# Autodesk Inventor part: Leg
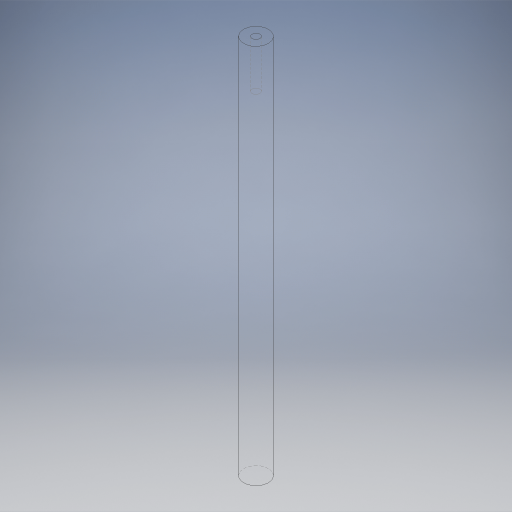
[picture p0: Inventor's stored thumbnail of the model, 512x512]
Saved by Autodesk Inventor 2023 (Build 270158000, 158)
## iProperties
Created: 2024-01
Part Number: Leg
Material: Generic
Document SubType Name: Modeling
Designer: tornqvih
Density: 1 g/cm^3
Appearance: Default
Author: tornqvih
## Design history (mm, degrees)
sketch "Sketch1"
  geometry: C1 r 6.5 at (0, 0); 1 further point
  constraints: 1 centre point, 1 coincident
  dimensions: "d0" = 13 diameter of C1
extrude "Extrusion1" new body sketch "Sketch1" distance "d1" = 200; taper "d2" = 0 deg
sketch "Sketch2"
  geometry: 2 further points
  constraints: 1 coincident
hole "Hole1" sketch "Sketch2" at (0, 0) diameter "d3" = 4.134; stored, may be unused: countersink angle "d7" = 90 deg, drill point angle "d9" = 118 deg; dims "d4" = 20, "d5" = 4, "d6" = 2, "d8" = 25
body "Solid1"
